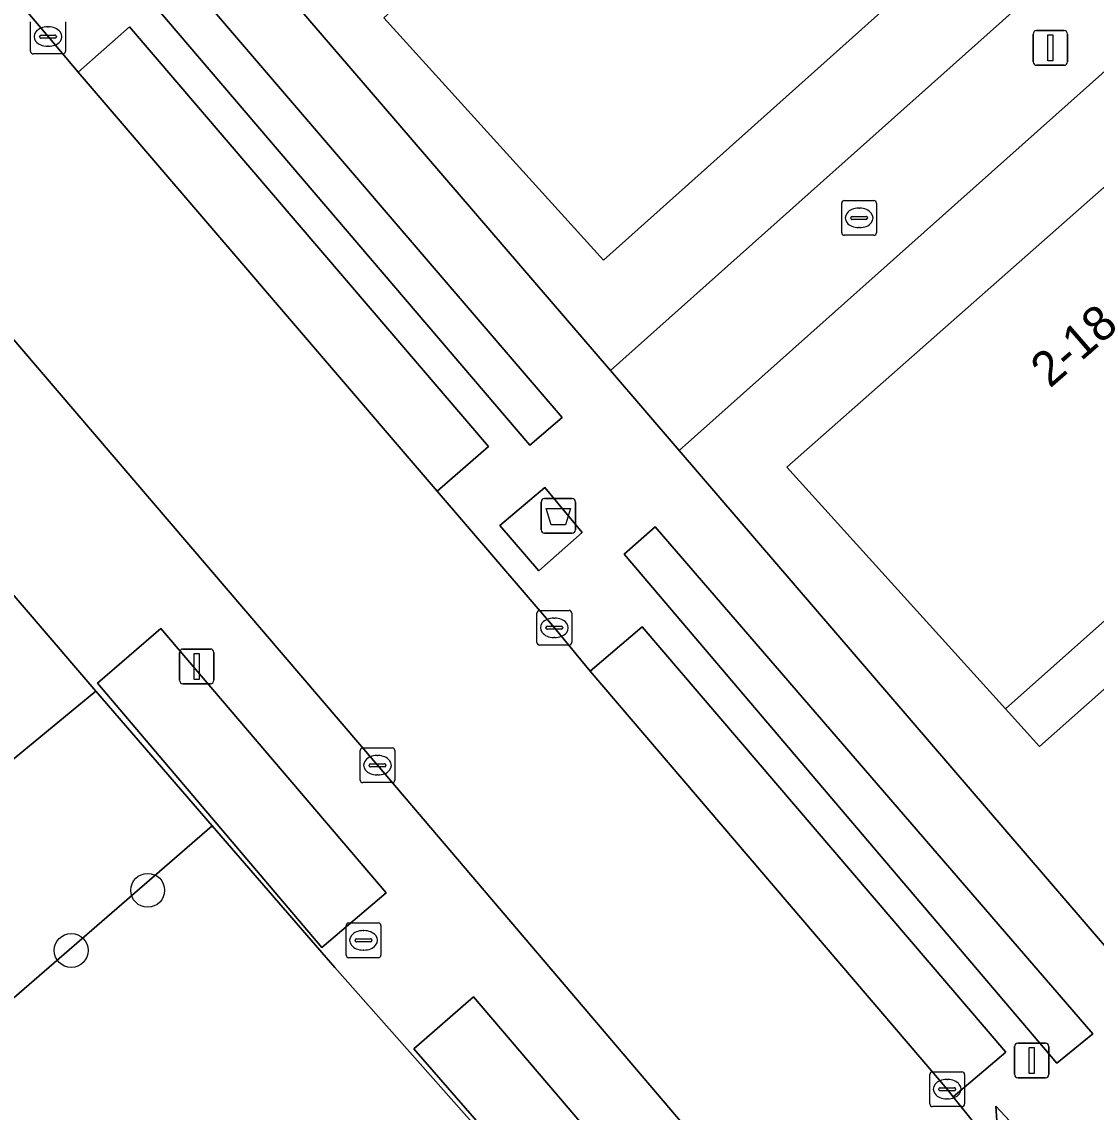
# Model space of a CAD drawing. Extents: x 162172 to 163187, y 382874 to 383685.
# Drawn here: x 162549.68 to 162580.64, y 383200.68 to 383232.09 of the extents above; entities that cross this region are included whole.
import ezdxf

# ---------------------------------------------------------------- set-up
doc = ezdxf.new("R2010")
doc.units = 0
for name, color, linetype in [('IMGEO_Afval_apart_plaats', 7, 'Continuous'), ('IMGEO_Boom', 7, 'Continuous'), ('IMGEO_Brandkraan', 7, 'Continuous'), ('IMGEO_Erf', 7, 'Continuous'), ('IMGEO_Groenvoorziening', 7, 'Continuous'), ('IMGEO_Kolk', 7, 'Continuous'), ('IMGEO_Lichtmast', 7, 'Continuous'), ('IMGEO_Pand', 7, 'Continuous'), ('IMGEO_Pand_nummerreeks', 7, 'Continuous'), ('IMGEO_Pand_overbouw', 7, 'Continuous'), ('IMGEO_Parkeervlak_open', 7, 'Continuous'), ('IMGEO_Rijbaan_lokaal_open', 7, 'Continuous'), ('IMGEO_Voetpad_gesloten', 7, 'Continuous'), ('IMGEO_Voetpad_open', 7, 'Continuous')]:
    doc.layers.add(name, color=color, linetype=linetype)

msp = doc.modelspace()

# ---------------------------------------------------------------- linework, layer by layer
at = {"layer": 'IMGEO_Afval_apart_plaats'}
for p, q in [((162564.645, 383217.458), (162564.645, 383218.258)), ((162564.645, 383218.258), (162564.645, 383217.458)), ((162564.745, 383218.358), (162565.535, 383218.358)), ((162565.535, 383218.358), (162564.745, 383218.358)), ((162565.635, 383218.258), (162565.635, 383217.458)), ((162565.635, 383217.458), (162565.635, 383218.258)), ((162565.535, 383217.358), (162564.745, 383217.358)), ((162564.745, 383217.358), (162565.535, 383217.358))]:
    msp.add_line(p, q, dxfattribs=at)
msp.add_lwpolyline([(162564.788, 383218.072), (162565.492, 383218.072), (162565.343, 383217.602), (162564.937, 383217.602), (162564.788, 383218.072)], dxfattribs=at)
for centre, start, end in [((162564.745, 383218.258), 90, 180), ((162564.745, 383218.258), 90, 180), ((162565.535, 383218.258), 0, 90), ((162565.535, 383218.258), 360, 90), ((162564.745, 383217.458), 180, 270), ((162564.745, 383217.458), 180, 270), ((162565.535, 383217.458), 270, 0), ((162565.535, 383217.458), 270, 0)]:
    msp.add_arc(centre, 0.1, start, end, dxfattribs=at)
at = {"layer": 'IMGEO_Boom'}
for centre in [(162553.307, 383207.073), (162551.105, 383205.342)]:
    msp.add_circle(centre, 0.489, dxfattribs=at)
at = {"layer": 'IMGEO_Brandkraan'}
for p, q in [((162559.026, 383205.206), (162559.026, 383206.058)), ((162559.101, 383206.132), (162559.953, 383206.132)), ((162560.027, 383206.058), (162560.027, 383205.206)), ((162559.514, 383205.912), (162559.539, 383205.912)), ((162559.285, 383205.626), (162559.285, 383205.638)), ((162559.723, 383205.589), (162559.325, 383205.589)), ((162559.328, 383205.675), (162559.726, 383205.675)), ((162559.769, 383205.638), (162559.769, 383205.626)), ((162559.953, 383205.132), (162559.101, 383205.132)), ((162559.537, 383205.352), (162559.512, 383205.352))]:
    msp.add_line(p, q, dxfattribs=at)
for points in [[(162559.026, 383205.206), (162559.026, 383206.058)], [(162559.101, 383206.132), (162559.953, 383206.132)], [(162560.027, 383206.058), (162560.027, 383205.206)], [(162559.953, 383205.132), (162559.101, 383205.132)]]:
    msp.add_lwpolyline(points, dxfattribs=at)
for centre, radius, start, end in [((162559.103, 383206.056), 0.0765, 91.552, 178.448), ((162559.103, 383206.056), 0.0765, 91.552, 178.448), ((162559.951, 383206.056), 0.0765, 1.552, 88.448), ((162559.951, 383206.056), 0.0765, 1.552, 88.448), ((162559.325, 383205.635), 0.0403, 85.8775, 175.7526), ((162559.322, 383205.625), 0.0366, 178.938, 274.7102), ((162559.726, 383205.632), 0.043, 264.8664, 352.4533), ((162559.73, 383205.637), 0.0386, 1.7309, 96.639), ((162559.103, 383205.208), 0.0765, 181.552, 268.448), ((162559.103, 383205.208), 0.0765, 181.552, 268.448), ((162559.951, 383205.208), 0.0765, 271.552, 358.448), ((162559.951, 383205.208), 0.0765, 271.552, 358.448)]:
    msp.add_arc(centre, radius, start, end, dxfattribs=at)
for centre, major_axis, ratio, start_param, end_param in [((162559.513, 383205.632), (-0.387, 0.002), 0.722429, 4.712389, 7.853982), ((162559.538, 383205.632), (-0.39, 0.002), 0.717154, 1.570796, 4.712389)]:
    msp.add_ellipse(centre, major_axis=major_axis, ratio=ratio, start_param=start_param, end_param=end_param, dxfattribs=at)
at = {"layer": 'IMGEO_Erf'}
for points in [[(162609.87, 383260.625), (162599.519, 383272.193), (162596.871, 383275.152), (162596.764, 383275.056), (162587.597, 383266.825), (162584.159, 383270.649), (162561.121, 383250), (162559.881, 383248.889), (162563.204, 383245.201), (162553.917, 383236.847), (162566.646, 383222.046), (162584.072, 383237.596)], [(162586.091, 383235.314), (162568.622, 383219.741), (162584.749, 383200.98)]]:
    msp.add_lwpolyline(points, dxfattribs=at)
for points in [[(162580.332, 383237.652), (162566.438, 383225.228), (162560.112, 383232.206), (162563.805, 383235.507), (162570.235, 383241.255), (162573.968, 383244.592), (162574.276, 383244.256)], [(162578.021, 383212.3), (162571.72, 383219.265), (162585.677, 383231.574), (162591.716, 383224.96), (162591.966, 383224.686), (162581.578, 383215.46)]]:
    msp.add_lwpolyline(points, close=True, dxfattribs=at)
at = {"layer": 'IMGEO_Groenvoorziening'}
for points in [[(162564.314, 383219.893), (162565.249, 383220.691), (162554.424, 383233.324), (162553.517, 383232.552)], [(162567.926, 383217.542), (162567.032, 383216.755), (162579.506, 383202.09), (162580.54, 383202.939)], [(162558.326, 383205.428), (162560.177, 383207.001), (162553.686, 383214.615), (162551.861, 383213.036)], [(162564.662, 383198.27), (162567.653, 383194.837), (162570.129, 383191.995), (162571.763, 383193.381), (162562.697, 383204.007), (162560.972, 383202.506)]]:
    msp.add_lwpolyline(points, close=True, dxfattribs=at)
at = {"layer": 'IMGEO_Kolk'}
for p, q in [((162549.934, 383231.238), (162549.934, 383232.09)), ((162550.935, 383232.09), (162550.935, 383231.238)), ((162550.422, 383231.944), (162550.447, 383231.944)), ((162550.193, 383231.658), (162550.193, 383231.67)), ((162550.631, 383231.621), (162550.233, 383231.621)), ((162550.236, 383231.707), (162550.634, 383231.707)), ((162550.677, 383231.67), (162550.677, 383231.658)), ((162550.861, 383231.164), (162550.009, 383231.164)), ((162550.445, 383231.384), (162550.42, 383231.384)), ((162573.305, 383226.015), (162573.305, 383226.867)), ((162573.38, 383226.941), (162574.232, 383226.941)), ((162574.306, 383226.867), (162574.306, 383226.015)), ((162573.564, 383226.435), (162573.564, 383226.447)), ((162573.607, 383226.484), (162574.005, 383226.484)), ((162573.793, 383226.721), (162573.818, 383226.721)), ((162574.048, 383226.447), (162574.048, 383226.435)), ((162574.002, 383226.398), (162573.604, 383226.398)), ((162573.816, 383226.161), (162573.791, 383226.161)), ((162574.232, 383225.941), (162573.38, 383225.941)), ((162564.598, 383215.135), (162565.45, 383215.135)), ((162564.523, 383214.209), (162564.523, 383215.061)), ((162565.011, 383214.915), (162565.036, 383214.915)), ((162565.524, 383215.061), (162565.524, 383214.209)), ((162564.782, 383214.629), (162564.782, 383214.641)), ((162565.22, 383214.592), (162564.822, 383214.592)), ((162564.825, 383214.678), (162565.223, 383214.678)), ((162565.266, 383214.641), (162565.266, 383214.629)), ((162565.034, 383214.355), (162565.009, 383214.355)), ((162565.45, 383214.135), (162564.598, 383214.135)), ((162559.428, 383210.249), (162559.428, 383211.101)), ((162559.503, 383211.175), (162560.355, 383211.175)), ((162560.429, 383211.101), (162560.429, 383210.249)), ((162559.73, 383210.718), (162560.128, 383210.718)), ((162559.916, 383210.955), (162559.941, 383210.955)), ((162559.687, 383210.669), (162559.687, 383210.681)), ((162560.125, 383210.632), (162559.727, 383210.632)), ((162560.171, 383210.681), (162560.171, 383210.669)), ((162560.355, 383210.175), (162559.503, 383210.175)), ((162559.939, 383210.395), (162559.914, 383210.395)), ((162575.842, 383200.919), (162575.842, 383201.771)), ((162575.917, 383201.845), (162576.769, 383201.845)), ((162576.33, 383201.625), (162576.355, 383201.625)), ((162576.843, 383201.771), (162576.843, 383200.919)), ((162576.101, 383201.339), (162576.101, 383201.351)), ((162576.539, 383201.302), (162576.141, 383201.302)), ((162576.144, 383201.388), (162576.542, 383201.388)), ((162576.585, 383201.351), (162576.585, 383201.339)), ((162576.353, 383201.065), (162576.328, 383201.065)), ((162576.769, 383200.845), (162575.917, 383200.845))]:
    msp.add_line(p, q, dxfattribs=at)
for points in [[(162549.934, 383231.238), (162549.934, 383232.09)], [(162550.935, 383232.09), (162550.935, 383231.238)], [(162550.861, 383231.164), (162550.009, 383231.164)], [(162573.305, 383226.015), (162573.305, 383226.867)], [(162573.38, 383226.941), (162574.232, 383226.941)], [(162574.306, 383226.867), (162574.306, 383226.015)], [(162574.232, 383225.941), (162573.38, 383225.941)], [(162564.598, 383215.135), (162565.45, 383215.135)], [(162564.523, 383214.209), (162564.523, 383215.061)], [(162565.524, 383215.061), (162565.524, 383214.209)], [(162565.45, 383214.135), (162564.598, 383214.135)], [(162559.428, 383210.249), (162559.428, 383211.101)], [(162559.503, 383211.175), (162560.355, 383211.175)], [(162560.429, 383211.101), (162560.429, 383210.249)], [(162560.355, 383210.175), (162559.503, 383210.175)], [(162575.842, 383200.919), (162575.842, 383201.771)], [(162575.917, 383201.845), (162576.769, 383201.845)], [(162576.843, 383201.771), (162576.843, 383200.919)], [(162576.769, 383200.845), (162575.917, 383200.845)]]:
    msp.add_lwpolyline(points, dxfattribs=at)
for centre, radius, start, end in [((162550.233, 383231.667), 0.0403, 85.8775, 175.7526), ((162550.23, 383231.657), 0.0366, 178.938, 274.7102), ((162550.634, 383231.664), 0.043, 264.8664, 352.4533), ((162550.638, 383231.669), 0.0386, 1.7309, 96.639), ((162550.011, 383231.24), 0.0765, 181.552, 268.448), ((162550.011, 383231.24), 0.0765, 181.552, 268.448), ((162550.859, 383231.24), 0.0765, 271.552, 358.448), ((162550.859, 383231.24), 0.0765, 271.552, 358.448), ((162573.382, 383226.865), 0.0765, 91.552, 178.448), ((162573.382, 383226.865), 0.0765, 91.552, 178.448), ((162574.23, 383226.865), 0.0765, 1.552, 88.448), ((162574.23, 383226.865), 0.0765, 1.552, 88.448), ((162573.604, 383226.444), 0.0403, 85.8775, 175.7526), ((162573.601, 383226.434), 0.0366, 178.938, 274.7102), ((162574.005, 383226.441), 0.043, 264.8664, 352.4533), ((162574.009, 383226.446), 0.0386, 1.7309, 96.639), ((162573.382, 383226.017), 0.0765, 181.552, 268.448), ((162573.382, 383226.017), 0.0765, 181.552, 268.448), ((162574.23, 383226.017), 0.0765, 271.552, 358.448), ((162574.23, 383226.017), 0.0765, 271.552, 358.448), ((162564.6, 383215.059), 0.0765, 91.552, 178.448), ((162564.6, 383215.059), 0.0765, 91.552, 178.448), ((162565.448, 383215.059), 0.0765, 1.552, 88.448), ((162565.448, 383215.059), 0.0765, 1.552, 88.448), ((162564.822, 383214.638), 0.0403, 85.8775, 175.7526), ((162564.819, 383214.628), 0.0366, 178.938, 274.7102), ((162565.223, 383214.635), 0.043, 264.8664, 352.4533), ((162565.227, 383214.64), 0.0386, 1.7309, 96.639), ((162564.6, 383214.211), 0.0765, 181.552, 268.448), ((162564.6, 383214.211), 0.0765, 181.552, 268.448), ((162565.448, 383214.211), 0.0765, 271.552, 358.448), ((162565.448, 383214.211), 0.0765, 271.552, 358.448), ((162559.505, 383211.099), 0.0765, 91.552, 178.448), ((162559.505, 383211.099), 0.0765, 91.552, 178.448), ((162560.353, 383211.099), 0.0765, 1.552, 88.448), ((162560.353, 383211.099), 0.0765, 1.552, 88.448), ((162559.727, 383210.678), 0.0403, 85.8775, 175.7526), ((162560.132, 383210.68), 0.0386, 1.7309, 96.639), ((162559.724, 383210.668), 0.0366, 178.938, 274.7102), ((162560.128, 383210.675), 0.043, 264.8664, 352.4533), ((162559.505, 383210.251), 0.0765, 181.552, 268.448), ((162559.505, 383210.251), 0.0765, 181.552, 268.448), ((162560.353, 383210.251), 0.0765, 271.552, 358.448), ((162560.353, 383210.251), 0.0765, 271.552, 358.448), ((162575.919, 383201.769), 0.0765, 91.552, 178.448), ((162575.919, 383201.769), 0.0765, 91.552, 178.448), ((162576.767, 383201.769), 0.0765, 1.552, 88.448), ((162576.767, 383201.769), 0.0765, 1.552, 88.448), ((162576.141, 383201.348), 0.0403, 85.8775, 175.7526), ((162576.138, 383201.338), 0.0366, 178.938, 274.7102), ((162576.542, 383201.345), 0.043, 264.8664, 352.4533), ((162576.546, 383201.35), 0.0386, 1.7309, 96.639), ((162575.919, 383200.921), 0.0765, 181.552, 268.448), ((162575.919, 383200.921), 0.0765, 181.552, 268.448), ((162576.767, 383200.921), 0.0765, 271.552, 358.448), ((162576.767, 383200.921), 0.0765, 271.552, 358.448)]:
    msp.add_arc(centre, radius, start, end, dxfattribs=at)
for centre, major_axis, ratio, start_param, end_param in [((162550.421, 383231.664), (-0.387, 0.002), 0.722429, 4.712389, 7.853982), ((162550.446, 383231.664), (-0.39, 0.002), 0.717154, 1.570796, 4.712389), ((162573.792, 383226.441), (-0.387, 0.002), 0.722429, 4.712389, 7.853982), ((162573.817, 383226.441), (-0.39, 0.002), 0.717154, 1.570796, 4.712389), ((162565.01, 383214.635), (-0.387, 0.002), 0.722429, 4.712389, 7.853982), ((162565.035, 383214.635), (-0.39, 0.002), 0.717154, 1.570796, 4.712389), ((162559.915, 383210.675), (-0.387, 0.002), 0.722429, 4.712389, 7.853982), ((162559.94, 383210.675), (-0.39, 0.002), 0.717154, 1.570796, 4.712389), ((162576.329, 383201.345), (-0.387, 0.002), 0.722429, 4.712389, 7.853982), ((162576.354, 383201.345), (-0.39, 0.002), 0.717154, 1.570796, 4.712389)]:
    msp.add_ellipse(centre, major_axis=major_axis, ratio=ratio, start_param=start_param, end_param=end_param, dxfattribs=at)
at = {"layer": 'IMGEO_Lichtmast'}
for p, q in [((162578.92, 383231.838), (162579.71, 383231.838)), ((162579.71, 383231.838), (162578.92, 383231.838)), ((162578.82, 383230.938), (162578.82, 383231.738)), ((162578.82, 383231.738), (162578.82, 383230.938)), ((162579.81, 383231.738), (162579.81, 383230.938)), ((162579.81, 383230.938), (162579.81, 383231.738)), ((162579.71, 383230.838), (162578.92, 383230.838)), ((162578.92, 383230.838), (162579.71, 383230.838)), ((162554.224, 383213.124), (162554.224, 383213.924)), ((162554.224, 383213.924), (162554.224, 383213.124)), ((162554.324, 383214.024), (162555.114, 383214.024)), ((162555.114, 383214.024), (162554.324, 383214.024)), ((162555.214, 383213.924), (162555.214, 383213.124)), ((162555.214, 383213.124), (162555.214, 383213.924)), ((162555.114, 383213.024), (162554.324, 383213.024)), ((162554.324, 383213.024), (162555.114, 383213.024)), ((162578.282, 383201.773), (162578.282, 383202.573)), ((162578.282, 383202.573), (162578.282, 383201.773)), ((162578.382, 383202.673), (162579.172, 383202.673)), ((162579.172, 383202.673), (162578.382, 383202.673)), ((162579.272, 383202.573), (162579.272, 383201.773)), ((162579.272, 383201.773), (162579.272, 383202.573)), ((162579.172, 383201.673), (162578.382, 383201.673)), ((162578.382, 383201.673), (162579.172, 383201.673))]:
    msp.add_line(p, q, dxfattribs=at)
for points in [[(162579.24, 383231.713), (162579.39, 383231.713), (162579.39, 383230.963), (162579.24, 383230.963), (162579.24, 383231.713)], [(162554.644, 383213.899), (162554.794, 383213.899), (162554.794, 383213.149), (162554.644, 383213.149), (162554.644, 383213.899)], [(162578.702, 383202.548), (162578.852, 383202.548), (162578.852, 383201.798), (162578.702, 383201.798), (162578.702, 383202.548)]]:
    msp.add_lwpolyline(points, dxfattribs=at)
for centre, start, end in [((162578.92, 383231.738), 90, 180), ((162578.92, 383231.738), 90, 180), ((162579.71, 383231.738), 0, 90), ((162579.71, 383231.738), 360, 90), ((162578.92, 383230.938), 180, 270), ((162578.92, 383230.938), 180, 270), ((162579.71, 383230.938), 270, 0), ((162579.71, 383230.938), 270, 0), ((162554.324, 383213.924), 90, 180), ((162554.324, 383213.924), 90, 180), ((162555.114, 383213.924), 0, 90), ((162555.114, 383213.924), 360, 90), ((162554.324, 383213.124), 180, 270), ((162554.324, 383213.124), 180, 270), ((162555.114, 383213.124), 270, 0), ((162555.114, 383213.124), 270, 0), ((162578.382, 383202.573), 90, 180), ((162578.382, 383202.573), 90, 180), ((162579.172, 383202.573), 0, 90), ((162579.172, 383202.573), 360, 90), ((162578.382, 383201.773), 180, 270), ((162578.382, 383201.773), 180, 270), ((162579.172, 383201.773), 270, 0), ((162579.172, 383201.773), 270, 0)]:
    msp.add_arc(centre, 0.1, start, end, dxfattribs=at)
at = {"layer": 'IMGEO_Pand'}
for points in [[(162580.332, 383237.652), (162574.276, 383244.256), (162573.968, 383244.592), (162570.235, 383241.255), (162563.805, 383235.507), (162560.112, 383232.206), (162566.438, 383225.228)], [(162591.966, 383224.686), (162591.716, 383224.96), (162585.677, 383231.574), (162571.72, 383219.265), (162578.021, 383212.3), (162581.578, 383215.46)]]:
    msp.add_lwpolyline(points, close=True, dxfattribs=at)
at = {"layer": 'IMGEO_Pand_overbouw'}
msp.add_lwpolyline([(162582.553, 383214.363), (162581.578, 383215.46), (162578.021, 383212.3), (162579.005, 383211.212)], close=True, dxfattribs=at)
at = {"layer": 'IMGEO_Parkeervlak_open'}
for points in [[(162551.306, 383230.635), (162561.643, 383218.568), (162563.122, 383219.859), (162552.781, 383231.949)], [(162566.057, 383213.383), (162576.343, 383201.345), (162576.518, 383201.126), (162578.035, 383202.407), (162567.551, 383214.667)], [(162555.167, 383208.933), (162551.809, 383212.814), (162545.407, 383207.537), (162548.798, 383203.422)]]:
    msp.add_lwpolyline(points, close=True, dxfattribs=at)
at = {"layer": 'IMGEO_Rijbaan_lokaal_open'}
for points in [[(162464.019, 383322.726), (162467.436, 383318.744), (162520.655, 383256.621), (162544.18, 383229.083), (162559.929, 383210.675), (162571.236, 383197.398), (162572.015, 383196.495), (162575.617, 383196.228), (162574.05, 383198.21), (162578.014, 383197.058), (162577.841, 383199.47), (162576.518, 383201.126), (162576.343, 383201.345), (162566.057, 383213.383), (162565.024, 383214.635), (162561.643, 383218.568), (162551.306, 383230.635), (162550.435, 383231.664), (162549.744, 383232.482)], [(162600.735, 383176.353), (162595.88, 383181.491), (162595.182, 383182.229), (162589.069, 383188.746), (162588.142, 383189.733), (162581.416, 383196.925), (162577.742, 383200.858), (162577.841, 383199.47), (162578.014, 383197.058), (162574.05, 383198.21), (162575.617, 383196.228), (162572.015, 383196.495), (162572.699, 383194.936)]]:
    msp.add_lwpolyline(points, dxfattribs=at)
at = {"layer": 'IMGEO_Voetpad_gesloten'}
msp.add_lwpolyline([(162564.753, 383218.678), (162563.454, 383217.578), (162564.576, 383216.276), (162565.828, 383217.379)], close=True, dxfattribs=at)
at = {"layer": 'IMGEO_Voetpad_open'}
for points in [[(162571.236, 383197.398), (162559.929, 383210.675), (162544.18, 383229.083), (162520.655, 383256.621)], [(162568.622, 383219.741), (162566.646, 383222.046), (162553.917, 383236.847), (162550.557, 383240.795), (162550.131, 383240.415)], [(162532.883, 383238.939), (162540.209, 383230.386), (162538.272, 383228.719), (162541.362, 383225.044), (162544.537, 383221.269), (162544.938, 383221.589), (162548.243, 383217.782), (162548.087, 383217.644), (162547.842, 383217.427), (162551.809, 383212.814), (162555.167, 383208.933), (162558.703, 383204.847), (162564.583, 383198.202)], [(162584.072, 383237.596), (162566.646, 383222.046), (162568.622, 383219.741), (162586.091, 383235.314)], [(162549.744, 383232.482), (162550.435, 383231.664), (162551.306, 383230.635), (162552.781, 383231.949), (162563.122, 383219.859), (162561.643, 383218.568), (162565.024, 383214.635), (162566.057, 383213.383), (162567.551, 383214.667), (162578.035, 383202.407), (162576.518, 383201.126), (162577.841, 383199.47), (162577.742, 383200.858), (162581.416, 383196.925), (162581.527, 383197.054)], [(162563.605, 383197.366), (162564.583, 383198.202), (162558.703, 383204.847), (162555.167, 383208.933), (162548.798, 383203.422), (162545.407, 383207.537), (162551.809, 383212.814), (162547.842, 383217.427), (162544.537, 383221.269), (162538.47, 383215.953), (162535.22, 383219.663), (162541.362, 383225.044), (162538.272, 383228.719), (162537.315, 383229.856), (162537.182, 383230.014), (162530.941, 383224.546), (162527.711, 383228.233), (162500, 383204.581)], [(162584.749, 383200.98), (162568.622, 383219.741)], [(162564.662, 383198.27), (162560.972, 383202.506), (162562.697, 383204.007), (162571.763, 383193.381)]]:
    msp.add_lwpolyline(points, dxfattribs=at)
for points in [[(162564.314, 383219.893), (162553.517, 383232.552), (162554.424, 383233.324), (162565.249, 383220.691)], [(162564.753, 383218.678), (162565.828, 383217.379), (162564.576, 383216.276), (162563.454, 383217.578)], [(162567.926, 383217.542), (162580.54, 383202.939), (162579.506, 383202.09), (162567.032, 383216.755)], [(162558.326, 383205.428), (162551.861, 383213.036), (162553.686, 383214.615), (162560.177, 383207.001)]]:
    msp.add_lwpolyline(points, close=True, dxfattribs=at)

# ---------------------------------------------------------------- texts
at = {"layer": 'IMGEO_Pand_nummerreeks'}
msp.add_text('2-18', height=1, rotation=40.9894, dxfattribs=at).set_placement((162579.302, 383221.518))

doc.saveas('drawing.dxf')
